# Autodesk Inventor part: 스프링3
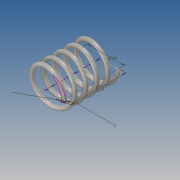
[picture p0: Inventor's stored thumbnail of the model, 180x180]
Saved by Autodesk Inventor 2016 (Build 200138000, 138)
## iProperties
Created: 2016-10
Part Number: 스프링3
Material: 강철, 탄소
Document SubType Name: Modeling
Designer: Administrator
Density: 7.85 g/cm^3
Appearance: 반연마
Mass: 6.86321 g
Surface Area: 17.7466 cm^2
Volume: 0.874294 cm^3
Author: Administrator
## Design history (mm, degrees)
sketch "스케치1"
  geometry: L1 (0, 0)-(-9, 0); L2 (-9, 0)-(-9, -27); L3 (-9, -27)-(0, -27); L4 (0, -27)-(0, 0); C1 r 1 at (-9, 0)
  constraints: 8 end point, 2 parallel, 1 centre point, 1 coincident, 1 horizontal, 1 perpendicular
  dimensions: "d0" = 2 diameter of C1; "d1" = 27 distance of L1.end L2.end (derived); "d2" = 18 diameter of L2 L4
feature "코일1" pitch "d3" = 10; turns "d5" = 5; dims "d4" = 27 (= d1), "d6" = 0, angle "d7" = 90 deg, angle "d8" = 90 deg, "d9" = 0, "d10" = 0
sketch "스케치2"
  geometry: L1 (10, 0)-(8, 0) reference; 1 further point
  constraints: 1 horizontal alignment
  node "절단 모서리 투영1"
extrude "돌출1" cut sketch "스케치2" stored distance "d11" = 10; taper "d12" = 0 deg
node "작업 평면3"
sketch "스케치3"
  geometry: L1 (-1, 0)-(1, 0) reference; 1 further point
  constraints: 1 horizontal alignment
extrude "돌출2" cut sketch "스케치3" stored distance "d14" = 0; taper "d15" = 0 deg
node "솔리드1"
node "절단 모서리 투영2"
other parameters: "d13" = 90 deg
